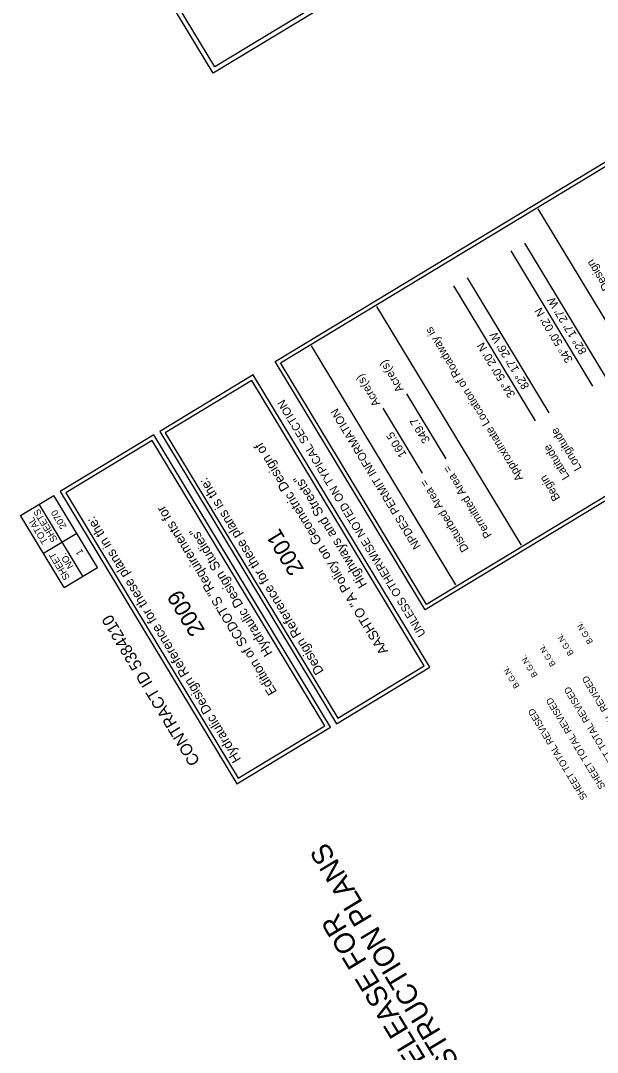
# Model space of a CAD drawing. Extents: x 2640307 to 2643631, y 679117 to 682232.
# Drawn here: x 2641641 to 2642063, y 680927 to 681682 of the extents above; entities that cross this region are included whole.
import ezdxf

# ---------------------------------------------------------------- set-up
doc = ezdxf.new("R2010")
doc.units = 0
for name, color, linetype in [('Level 42', 7, 'Continuous'), ('RD_SHT_Bndy', 7, 'Continuous'), ('RD_SHT_TX', 7, 'Continuous'), ('RD_SHT_TX_FINAL', 7, 'Continuous')]:
    doc.layers.add(name, color=color, linetype=linetype)

msp = doc.modelspace()

# ---------------------------------------------------------------- linework, layer by layer
at = {"layer": 'Level 42'}
for points in [[(2641781.92, 681643.61), (2641672.07, 681825.33), (2641946.25, 681991.07), (2642056.1, 681809.34)], [(2641783.1, 681648.41), (2641676.88, 681824.15), (2641945.07, 681986.26), (2642051.29, 681810.53)], [(2641937.06, 681250.85), (2641827.21, 681432.57), (2642101.4, 681598.31), (2642211.24, 681416.58)], [(2641938.02, 681254.75), (2641831.11, 681431.61), (2642100.43, 681594.41), (2642207.34, 681417.54)]]:
    msp.add_lwpolyline(points, close=True, dxfattribs=at)
at = {"layer": 'RD_SHT_Bndy'}
for p, q in [((2642019.66, 681544.31), (2642125.24, 681369.63)), ((2642007.61, 681298.28), (2641901.74, 681472.9)), ((2641959.53, 681269.25), (2641853.85, 681444.12)), ((2641640.99, 681320.01), (2641665.28, 681334.69)), ((2641686.48, 681275.44), (2641654.58, 681328.22)), ((2641657.74, 681292.28), (2641682.03, 681306.97)), ((2641672.89, 681267.23), (2641697.18, 681281.91))]:
    msp.add_line(p, q, dxfattribs=at)
for points in [[(2641940.56, 681208.97), (2641811.24, 681422.92), (2641742.77, 681381.53), (2641872.1, 681167.58)], [(2641936.44, 681209.98), (2641810.22, 681418.8), (2641746.89, 681380.52), (2641873.11, 681171.7)], [(2641867.72, 681164.93), (2641738.39, 681378.88), (2641669.93, 681337.5), (2641799.25, 681123.55)], [(2641863.6, 681165.95), (2641737.37, 681374.77), (2641674.05, 681336.48), (2641800.27, 681127.67)]]:
    msp.add_lwpolyline(points, close=True, dxfattribs=at)
at = {"layer": 'RD_SHT_TX'}
for p, q in [((2642069.97, 681420.48), (2642010.19, 681519.37)), ((2642059.95, 681414.66), (2642000.17, 681513.55)), ((2642027.85, 681395.02), (2641968.07, 681493.91)), ((2642017.83, 681389.2), (2641958.05, 681488.09)), ((2641952.38, 681361.43), (2641923.64, 681408.97)), ((2641935.15, 681351.02), (2641906.42, 681398.56)), ((2641697.18, 681281.91), (2641665.28, 681334.69)), ((2641672.89, 681267.23), (2641640.99, 681320.01))]:
    msp.add_line(p, q, dxfattribs=at)

# ---------------------------------------------------------------- texts
at = {"layer": 'RD_SHT_Bndy'}
for s, height, p in [('UNLESS OTHERWISE NOTED ON TYPICAL SECTION', 6, (2641937.71, 681233.26)), ('AASHTO "A Policy on Geometric Design of ', 7, (2641910.25, 681220.68)), ('Design Reference for these plans is the:', 7, (2641863.12, 681205.87)), ('Highways and Streets"', 7, (2641894.85, 681269.36)), ('Edition of SCDOT\'S "Requirements for', 7, (2641828.76, 681190.95)), ('Hydraulic Design Reference for these plans in the:', 7, (2641802.57, 681141.5)), ('2001', 12, (2641848.8, 681280.63)), ('Hydraulic Design Studies"', 7, (2641825.65, 681219.3)), ('2009', 12, (2641776.25, 681236.1))]:
    msp.add_text(s, height=height, rotation=121.15134, dxfattribs=at).set_placement(p)
at = {"layer": 'RD_SHT_TX'}
for s, height, p in [('Hydraulic and NPDES Design', 6, (2642114.72, 681417.12)), ("82° 17' 27' W", 6, (2642055.73, 681439.98)), ("34° 50' 02' N", 6, (2642045.49, 681433.79)), ('Approximate Location of Roadway is', 6, (2642009.15, 681347.13)), ("34° 50' 20' N", 6, (2642003.37, 681408.33)), ("82° 17' 26' W", 6, (2642013.61, 681414.52)), ('Acre(s)', 6, (2641921.6, 681412.28)), ('Acre(s)', 6, (2641904.37, 681401.86)), ('NPDES PERMIT INFORMATION', 6, (2641934.08, 681297.44)), ('349.7', 6, (2641940.96, 681374.97)), ('160.5', 6, (2641923.73, 681364.56)), ('Longitude', 6, (2642051.95, 681354.72)), ('Latitude', 6, (2642043.05, 681348.26)), ('Permitted Area = ', 6, (2641986.14, 681305.5)), ('Begin', 6, (2642036.13, 681332.63)), ('Disturbed Area = ', 6, (2641969.26, 681295.29)), ('TOTAL', 5, (2641661.29, 681300.89)), ('SHEETS', 5, (2641668.2, 681302.31)), ('2070', 5, (2641674.82, 681311.88)), ('1', 5, (2641687.12, 681292.79)), ('SHEET', 5, (2641677.26, 681274.47)), ('NO.', 5, (2641679.99, 681282.82)), ('CONTRACT ID 5384210', 8.5949, (2641772.6, 681139.97)), ('B.G.N.', 4.4, (2642060.2, 681227.53)), ('B.G.N.', 4.4, (2642045.99, 681218.94)), ('B.G.N.', 4.4, (2642032.8, 681210.97)), ('B.G.N.', 4.4, (2642019.61, 681203)), ('B.G.N.', 4.4, (2642006.42, 681195.02)), ('SHEET TOTAL REVISED', 5, (2642095.6, 681137.44)), ('SHEET TOTAL REVISED', 5, (2642082.41, 681129.47)), ('SHEET TOTAL REVISED', 5, (2642069.22, 681121.49)), ('SHEET TOTAL REVISED', 5, (2642056.03, 681113.52))]:
    msp.add_text(s, height=height, rotation=121.15134, dxfattribs=at).set_placement(p)
at = {"layer": 'RD_SHT_TX_FINAL'}
for s, p in [('CONSTRUCTION PLANS', (2641985.33, 680882.16)), ('RELEASE FOR', (2641945.63, 680909.82))]:
    msp.add_text(s, height=15, rotation=121.15134, dxfattribs=at).set_placement(p)

doc.saveas('drawing.dxf')
